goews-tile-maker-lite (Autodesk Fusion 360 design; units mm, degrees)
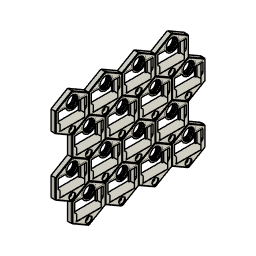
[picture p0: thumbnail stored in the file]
parameter "verticalspacing" = 72.746
parameter "horizontalSpacing" = 42
base_feature "Base Feature1" bodies "GOEWS Lite", "Hex (1)"
copy_paste_bodies "CopyPasteBodies1"
move "Move1"
align "Align1"
combine "Combine1" bodies "GOEWS Lite"
sketch "Sketch1" plane through (0, 0, 0) normal (1, 0, 0) x axis (0, 1, 0)
  line L1 (-15.5, -12.1244) -> (15.5, -12.1244)
  line L2 (-15.5, -4.1244) -> (-15.5, -12.1244)
  line L3 (-18, -1.6244) -> (-15.5, -4.1244)
  line L4 (-18, 9.8756) -> (-18, -1.6244)
  line L5 (-8.5448, 9.8756) -> (-18, 9.8756)
  line L6 (18, 9.8756) -> (8.5448, 9.8756)
  line L7 (18, -1.6244) -> (18, 9.8756)
  line L8 (15.5, -4.1244) -> (18, -1.6244)
  line L9 (15.5, -12.1244) -> (15.5, -4.1244)
  line L10 (0, -23.6714) -> (-20.5, -11.8357)
  line L11 (20.5, -11.8357) -> (0, -23.6714)
  line L12 (20.5, 11.8357) -> (20.5, -11.8357)
  line L13 (0, 23.6714) -> (20.5, 11.8357)
  line L14 (-20.5, 11.8357) -> (0, 23.6714)
  line L15 (-20.5, -11.8357) -> (-20.5, 11.8357)
  arc A1 centre (0, 12.7017) radius 9 clockwise from (8.5448, 9.8756) to (-8.5448, 9.8756)
  circle C1 centre (0, 12.7017) radius 7.1612
  circle C2 centre (0, -18.2487) radius 4
  point P20 (0, -24.2487)
  point P21 (-21, 60.6218)
  point P22 (-21, -12.1244)
  dimension "d64" distance P20 P21 = 84.8705
  dimension "d65" distance P21 P22 = 72.7461
rectangular_pattern "R-Pattern1" bodies "GOEWS Lite Pair (1)", "GOEWS Lite Pair (2)", "GOEWS Lite Pair (9)", "GOEWS Lite Pair (3)", "GOEWS Lite Pair (4)", "GOEWS Lite Pair (5)", "GOEWS Lite Pair (18)"
combine "Combine2" bodies "GOEWS Lite Pair (3)", "GOEWS Lite Pair (9)", "GOEWS Lite Pair (1)", "GOEWS Lite Pair (4)", "GOEWS Lite Pair (2)", "GOEWS Lite Pair (18)", "GOEWS Lite Pair (5)"
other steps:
base_feature "Base Feature2" bodies "GOEWS Lite", "GOEWS Lite Pair"
named bodies: "GOEWS Lite", "Hex (1)", "GOEWS Lite Pair", "GOEWS Lite Pair (1)", "GOEWS Lite Pair (2)", "GOEWS Lite Pair (3)", "GOEWS Lite Pair (4)", "GOEWS Lite Pair (5)", "GOEWS Lite Pair (9)", "GOEWS Lite Pair (18)"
